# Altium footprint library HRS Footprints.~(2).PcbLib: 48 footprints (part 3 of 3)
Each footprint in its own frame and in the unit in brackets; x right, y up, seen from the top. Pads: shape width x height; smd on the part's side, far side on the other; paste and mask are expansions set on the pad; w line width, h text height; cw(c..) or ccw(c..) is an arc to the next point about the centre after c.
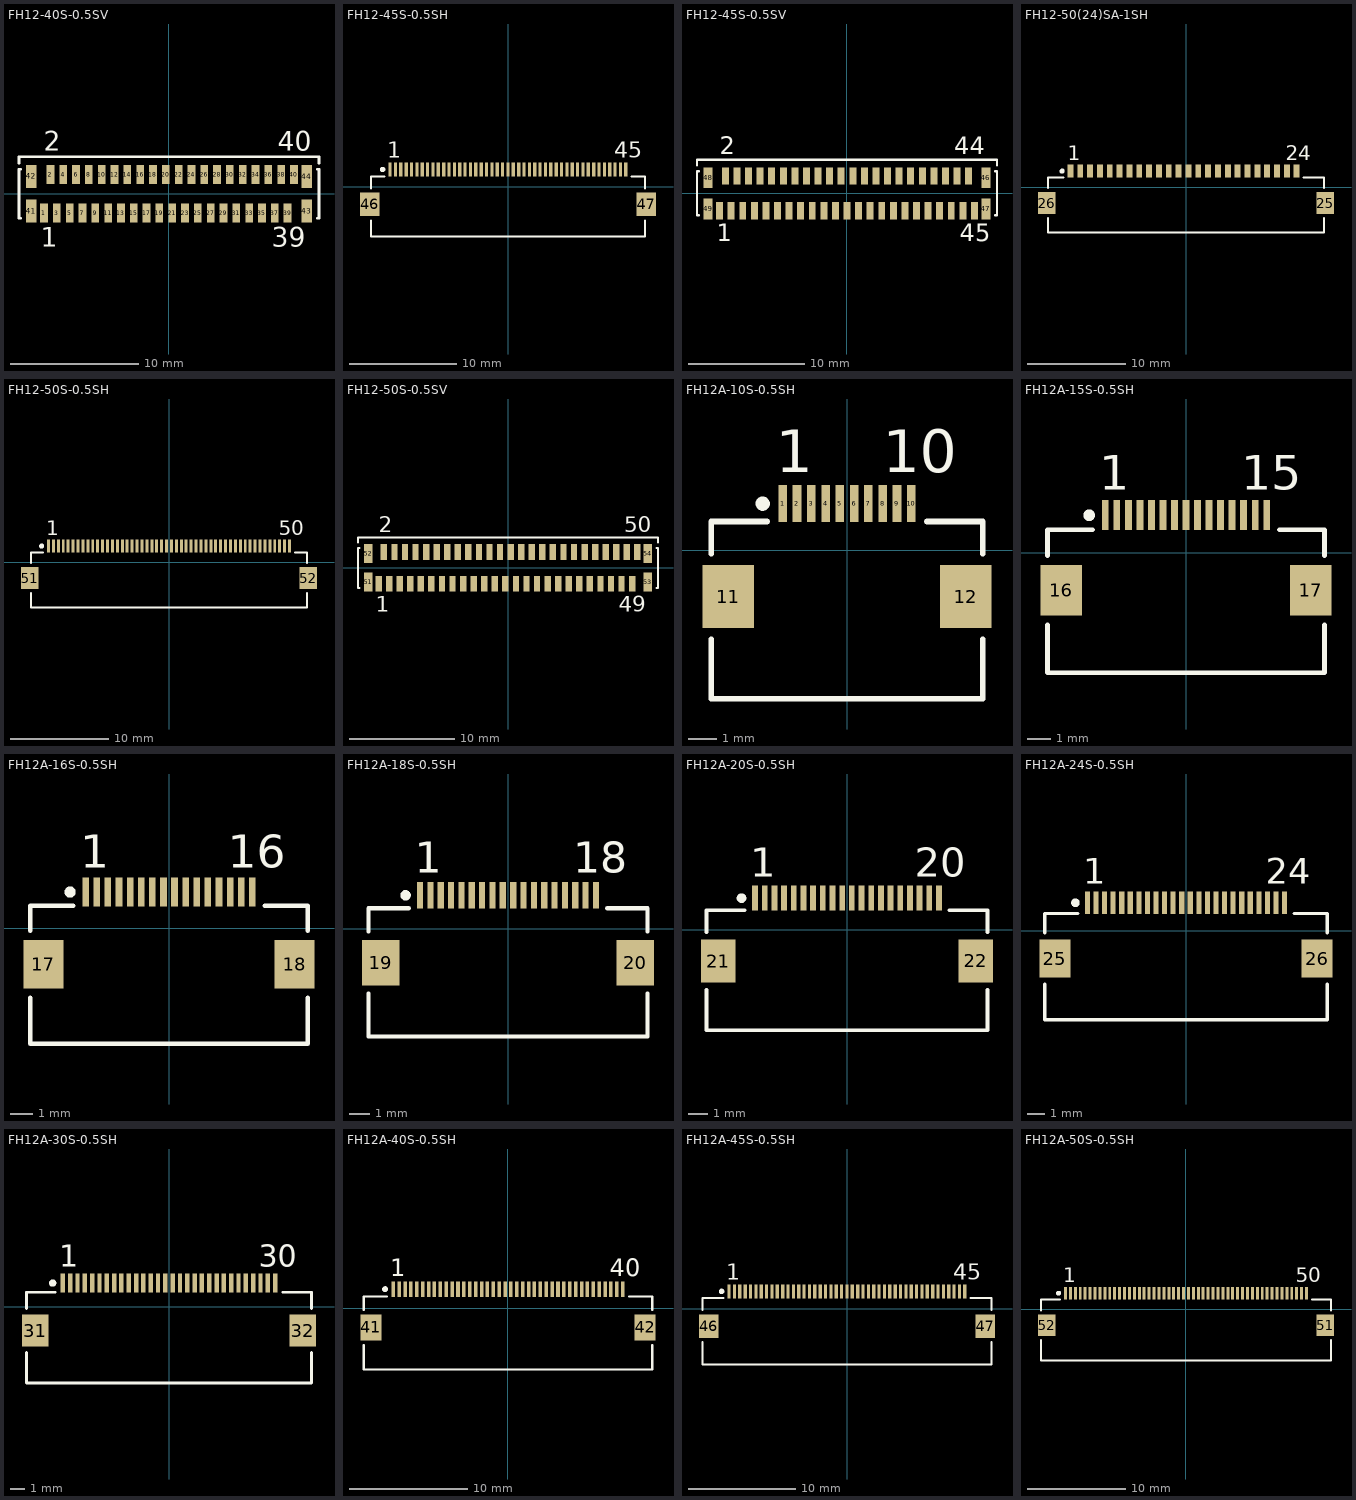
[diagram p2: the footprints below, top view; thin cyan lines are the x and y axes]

## FH12-40S-0.5SV [mm] "Connector; FH12 Series; 40 Position; 0.5mm Spaced Vertical Mounting"
height 4.85
pads (44):
  rect 0.6x1.5 smd: 1(-9.75,-1.5) 2(-9.25,1.5) 3(-8.75,-1.5) 4(-8.25,1.5) 5(-7.75,-1.5) 6(-7.25,1.5) 7(-6.75,-1.5) 8(-6.25,1.5) 9(-5.75,-1.5) 10(-5.25,1.5) 11(-4.75,-1.5) 12(-4.25,1.5) 13(-3.75,-1.5) 14(-3.25,1.5) 15(-2.75,-1.5) 16(-2.25,1.5) 17(-1.75,-1.5) 18(-1.25,1.5) 19(-0.75,-1.5) 20(-0.25,1.5) 21(0.25,-1.5) 22(0.75,1.5) 23(1.25,-1.5) 24(1.75,1.5) 25(2.25,-1.5) 26(2.75,1.5) 27(3.25,-1.5) 28(3.75,1.5) 29(4.25,-1.5) 30(4.75,1.5) 31(5.25,-1.5) 32(5.75,1.5) 33(6.25,-1.5) 34(6.75,1.5) 35(7.25,-1.5) 36(7.75,1.5) 37(8.25,-1.5) 38(8.75,1.5) 39(9.25,-1.5) 40(9.75,1.5)
  rect 0.8x1.8 smd: 41(-10.75,-1.35) 42(-10.75,1.35) 43(10.75,-1.35) 44(10.75,1.35)
Top Overlay:
  lines w0.2: -11.7,2.4 -11.7,2.9 11.7,2.9 11.7,2.4 ; -11.55,-1.9 -11.7,-1.9 -11.7,1.9 -11.55,1.9 ; 11.55,-1.9 11.7,-1.9 11.7,1.9 11.55,1.9
  text "39" at 8,-4.125 h1.5
  text "40" at 8.5,3.375 h1.5
  text "2" at -9.75,3.375 h1.5
  text "1" at -10,-4.125 h1.5

## FH12-45S-0.5SH [mm] "Connector; FH12 Series; 45 Position; 0.5mm Spaced Bottom Contact"
height 2
pads (47):
  rect 0.3x1.3 smd: 1(-11,1.625) 2(-10.5,1.625) 3(-10,1.625) 4(-9.5,1.625) 5(-9,1.625) 6(-8.5,1.625) 7(-8,1.625) 8(-7.5,1.625) 9(-7,1.625) 10(-6.5,1.625) 11(-6,1.625) 12(-5.5,1.625) 13(-5,1.625) 14(-4.5,1.625) 15(-4,1.625) 16(-3.5,1.625) 17(-3,1.625) 18(-2.5,1.625) 19(-2,1.625) 20(-1.5,1.625) 21(-1,1.625) 22(-0.5,1.625) 23(0,1.625) 24(0.5,1.625) 25(1,1.625) 26(1.5,1.625) 27(2,1.625) 28(2.5,1.625) 29(3,1.625) 30(3.5,1.625) 31(4,1.625) 32(4.5,1.625) 33(5,1.625) 34(5.5,1.625) 35(6,1.625) 36(6.5,1.625) 37(7,1.625) 38(7.5,1.625) 39(8,1.625) 40(8.5,1.625) 41(9,1.625) 42(9.5,1.625) 43(10,1.625) 44(10.5,1.625) 45(11,1.625)
  rect 1.8x2.2 smd: 46(-12.9,-1.625) 47(12.9,-1.625)
Top Overlay:
  circle w0.25: c-11.7,1.625 r0.125
  lines w0.2: -12.8,-3.125 -12.8,-4.625 12.8,-4.625 12.8,-3.125 ; -12.8,-0.125 -12.8,0.975 -11.55,0.975 ; 11.55,0.975 12.8,0.975 12.8,-0.125
  text "1" at -11.25,2.725 h1.5
  text "45" at 9.9,2.725 h1.5

## FH12-45S-0.5SV [mm] "Connector; FH12 Series; 45 Position; 0.5mm Spaced Vertical Mounting"
height 4.85
pads (49):
  rect 0.6x1.5 smd: 1(-11,-1.5) 2(-10.5,1.5) 3(-10,-1.5) 4(-9.5,1.5) 5(-9,-1.5) 6(-8.5,1.5) 7(-8,-1.5) 8(-7.5,1.5) 9(-7,-1.5) 10(-6.5,1.5) 11(-6,-1.5) 12(-5.5,1.5) 13(-5,-1.5) 14(-4.5,1.5) 15(-4,-1.5) 16(-3.5,1.5) 17(-3,-1.5) 18(-2.5,1.5) 19(-2,-1.5) 20(-1.5,1.5) 21(-1,-1.5) 22(-0.5,1.5) 23(0,-1.5) 24(0.5,1.5) 25(1,-1.5) 26(1.5,1.5) 27(2,-1.5) 28(2.5,1.5) 29(3,-1.5) 30(3.5,1.5) 31(4,-1.5) 32(4.5,1.5) 33(5,-1.5) 34(5.5,1.5) 35(6,-1.5) 36(6.5,1.5) 37(7,-1.5) 38(7.5,1.5) 39(8,-1.5) 40(8.5,1.5) 41(9,-1.5) 42(9.5,1.5) 43(10,-1.5) 44(10.5,1.5) 45(11,-1.5)
  rect 0.8x1.8 smd: 46(12,1.35) 47(12,-1.35) 48(-12,1.35) 49(-12,-1.35)
Top Overlay:
  lines w0.2: -12.95,2.4 -12.95,2.9 12.95,2.9 12.95,2.4 ; -12.8,-1.9 -12.95,-1.9 -12.95,1.9 -12.8,1.9 ; 12.8,-1.9 12.95,-1.9 12.95,1.9 12.8,1.9
  text "45" at 9.75,-4.125 h1.5
  text "44" at 9.25,3.375 h1.5
  text "1" at -11.25,-4.125 h1.5
  text "2" at -11,3.375 h1.5

## FH12-50(24)SA-1SH [mm] "Connector; FH12 Series; 24 Position; 1.0mm Spaced Bottom Eccentric Contact"
height 2
pads (26):
  rect 0.6x1.3 smd: 1(-11.75,1.625) 2(-10.75,1.625) 3(-9.75,1.625) 4(-8.75,1.625) 5(-7.75,1.625) 6(-6.75,1.625) 7(-5.75,1.625) 8(-4.75,1.625) 9(-3.75,1.625) 10(-2.75,1.625) 11(-1.75,1.625) 12(-0.75,1.625) 13(0.25,1.625) 14(1.25,1.625) 15(2.25,1.625) 16(3.25,1.625) 17(4.25,1.625) 18(5.25,1.625) 19(6.25,1.625) 20(7.25,1.625) 21(8.25,1.625) 22(9.25,1.625) 23(10.25,1.625) 24(11.25,1.625)
  rect 1.8x2.2 smd: 25(14.15,-1.625) 26(-14.15,-1.625)
Top Overlay:
  circle w0.25: c-12.6,1.625 r0.125
  lines w0.2: -14.05,-3.125 -14.05,-4.625 14.05,-4.625 14.05,-3.125 ; -14.05,-0.125 -14.05,0.975 -12.45,0.975 ; 11.95,0.975 14.05,0.975 14.05,-0.125
  text "24" at 10.15,2.725 h1.5
  text "1" at -12,2.725 h1.5

## FH12-50S-0.5SH [mm] "Connector; FH12 Series; 50 Position; 0.5mm Spaced Bottom Contact"
height 2
pads (52):
  rect 0.3x1.3 smd: 1(-12.25,1.625) 2(-11.75,1.625) 3(-11.25,1.625) 4(-10.75,1.625) 5(-10.25,1.625) 6(-9.75,1.625) 7(-9.25,1.625) 8(-8.75,1.625) 9(-8.25,1.625) 10(-7.75,1.625) 11(-7.25,1.625) 12(-6.75,1.625) 13(-6.25,1.625) 14(-5.75,1.625) 15(-5.25,1.625) 16(-4.75,1.625) 17(-4.25,1.625) 18(-3.75,1.625) 19(-3.25,1.625) 20(-2.75,1.625) 21(-2.25,1.625) 22(-1.75,1.625) 23(-1.25,1.625) 24(-0.75,1.625) 25(-0.25,1.625) 26(0.25,1.625) 27(0.75,1.625) 28(1.25,1.625) 29(1.75,1.625) 30(2.25,1.625) 31(2.75,1.625) 32(3.25,1.625) 33(3.75,1.625) 34(4.25,1.625) 35(4.75,1.625) 36(5.25,1.625) 37(5.75,1.625) 38(6.25,1.625) 39(6.75,1.625) 40(7.25,1.625) 41(7.75,1.625) 42(8.25,1.625) 43(8.75,1.625) 44(9.25,1.625) 45(9.75,1.625) 46(10.25,1.625) 47(10.75,1.625) 48(11.25,1.625) 49(11.75,1.625) 50(12.25,1.625)
  rect 1.8x2.2 smd: 51(-14.15,-1.625) 52(14.15,-1.625)
Top Overlay:
  circle w0.25: c-12.95,1.625 r0.125
  lines w0.2: -14.05,-3.125 -14.05,-4.625 14.05,-4.625 14.05,-3.125 ; -14.05,-0.125 -14.05,0.975 -12.8,0.975 ; 12.8,0.975 14.05,0.975 14.05,-0.125
  text "50" at 11.15,2.725 h1.5
  text "1" at -12.5,2.725 h1.5
3D body: height 2.04, standoff -0.06, extent -14.55,-4.699 14.55,1.701

## FH12-50S-0.5SV [mm] "Connector; FH12 Series; 50 Position; 0.5mm Spaced Vertical Mounting"
height 4.85
pads (54):
  rect 0.6x1.5 smd: 1(-12.25,-1.5) 2(-11.75,1.5) 3(-11.25,-1.5) 4(-10.75,1.5) 5(-10.25,-1.5) 6(-9.75,1.5) 7(-9.25,-1.5) 8(-8.75,1.5) 9(-8.25,-1.5) 10(-7.75,1.5) 11(-7.25,-1.5) 12(-6.75,1.5) 13(-6.25,-1.5) 14(-5.75,1.5) 15(-5.25,-1.5) 16(-4.75,1.5) 17(-4.25,-1.5) 18(-3.75,1.5) 19(-3.25,-1.5) 20(-2.75,1.5) 21(-2.25,-1.5) 22(-1.75,1.5) 23(-1.25,-1.5) 24(-0.75,1.5) 25(-0.25,-1.5) 26(0.25,1.5) 27(0.75,-1.5) 28(1.25,1.5) 29(1.75,-1.5) 30(2.25,1.5) 31(2.75,-1.5) 32(3.25,1.5) 33(3.75,-1.5) 34(4.25,1.5) 35(4.75,-1.5) 36(5.25,1.5) 37(5.75,-1.5) 38(6.25,1.5) 39(6.75,-1.5) 40(7.25,1.5) 41(7.75,-1.5) 42(8.25,1.5) 43(8.75,-1.5) 44(9.25,1.5) 45(9.75,-1.5) 46(10.25,1.5) 47(10.75,-1.5) 48(11.25,1.5) 49(11.75,-1.5) 50(12.25,1.5)
  rect 0.8x1.8 smd: 51(-13.25,-1.35) 52(-13.25,1.35) 53(13.25,-1.35) 54(13.25,1.35)
Top Overlay:
  lines w0.2: -14.2,2.4 -14.2,2.9 14.2,2.9 14.2,2.4 ; -14.05,-1.9 -14.2,-1.9 -14.2,1.9 -14.05,1.9 ; 14.05,-1.9 14.2,-1.9 14.2,1.9 14.05,1.9
  text "50" at 11,3.375 h1.5
  text "49" at 10.5,-4.125 h1.5
  text "2" at -12.25,3.375 h1.5
  text "1" at -12.5,-4.125 h1.5

## FH12A-10S-0.5SH [mm] "Connector; FH12 Series; 10 Position; 0.5mm Spaced Top Contact"
height 2
pads (12):
  rect 0.3x1.3 smd: 1(-2.25,1.625) 2(-1.75,1.625) 3(-1.25,1.625) 4(-0.75,1.625) 5(-0.25,1.625) 6(0.25,1.625) 7(0.75,1.625) 8(1.25,1.625) 9(1.75,1.625) 10(2.25,1.625)
  rect 1.8x2.2 smd: 11(-4.15,-1.625) 12(4.15,-1.625)
Top Overlay:
  circle w0.25: c-2.95,1.625 r0.125
  lines w0.2: -4.75,-3.125 -4.75,-5.2 4.75,-5.2 4.75,-3.125 ; -4.75,-0.125 -4.75,1 -2.8,1 ; 2.8,1 4.75,1 4.75,-0.125
  text "10" at 1.25,2.725 h1.5
  text "1" at -2.5,2.725 h1.5

## FH12A-15S-0.5SH [mm] "Connector; FH12 Series; 15 Position; 0.5mm Spaced Top Contact"
height 2
pads (17):
  rect 0.3x1.3 smd: 1(-3.5,1.625) 2(-3,1.625) 3(-2.5,1.625) 4(-2,1.625) 5(-1.5,1.625) 6(-1,1.625) 7(-0.5,1.625) 8(0,1.625) 9(0.5,1.625) 10(1,1.625) 11(1.5,1.625) 12(2,1.625) 13(2.5,1.625) 14(3,1.625) 15(3.5,1.625)
  rect 1.8x2.2 smd: 16(-5.4,-1.625) 17(5.4,-1.625)
Top Overlay:
  circle w0.25: c-4.2,1.625 r0.125
  lines w0.2: -6,-3.125 -6,-5.2 6,-5.2 6,-3.125 ; -6,-0.125 -6,1 -4.05,1 ; 4.05,1 6,1 6,-0.125
  text "1" at -3.75,2.725 h1.5
  text "15" at 2.4,2.725 h1.5

## FH12A-16S-0.5SH [mm] "Connector; FH12 Series; 16 Position; 0.5mm Spaced Top Contact"
height 2
pads (18):
  rect 0.3x1.3 smd: 1(-3.75,1.625) 2(-3.25,1.625) 3(-2.75,1.625) 4(-2.25,1.625) 5(-1.75,1.625) 6(-1.25,1.625) 7(-0.75,1.625) 8(-0.25,1.625) 9(0.25,1.625) 10(0.75,1.625) 11(1.25,1.625) 12(1.75,1.625) 13(2.25,1.625) 14(2.75,1.625) 15(3.25,1.625) 16(3.75,1.625)
  rect 1.8x2.2 smd: 17(-5.65,-1.625) 18(5.65,-1.625)
Top Overlay:
  circle w0.25: c-4.45,1.625 r0.125
  lines w0.2: -6.25,-3.125 -6.25,-5.2 6.25,-5.2 6.25,-3.125 ; -6.25,-0.125 -6.25,1 -4.3,1 ; 4.3,1 6.25,1 6.25,-0.125
  text "16" at 2.65,2.725 h1.5
  text "1" at -4,2.725 h1.5

## FH12A-18S-0.5SH [mm] "Connector; FH12 Series; 18 Position; 0.5mm Spaced Top Contact"
height 2
pads (20):
  rect 0.3x1.3 smd: 1(-4.25,1.625) 2(-3.75,1.625) 3(-3.25,1.625) 4(-2.75,1.625) 5(-2.25,1.625) 6(-1.75,1.625) 7(-1.25,1.625) 8(-0.75,1.625) 9(-0.25,1.625) 10(0.25,1.625) 11(0.75,1.625) 12(1.25,1.625) 13(1.75,1.625) 14(2.25,1.625) 15(2.75,1.625) 16(3.25,1.625) 17(3.75,1.625) 18(4.25,1.625)
  rect 1.8x2.2 smd: 19(-6.15,-1.625) 20(6.15,-1.625)
Top Overlay:
  circle w0.25: c-4.95,1.625 r0.125
  lines w0.2: -6.75,-3.125 -6.75,-5.2 6.75,-5.2 6.75,-3.125 ; -6.75,-0.125 -6.75,1 -4.8,1 ; 4.8,1 6.75,1 6.75,-0.125
  text "1" at -4.5,2.725 h1.5
  text "18" at 3.15,2.725 h1.5

## FH12A-20S-0.5SH [mm] "Connector; FH12 Series; 20 Position; 0.5mm Spaced Top Contact"
height 2
pads (22):
  rect 0.3x1.3 smd: 1(-4.75,1.625) 2(-4.25,1.625) 3(-3.75,1.625) 4(-3.25,1.625) 5(-2.75,1.625) 6(-2.25,1.625) 7(-1.75,1.625) 8(-1.25,1.625) 9(-0.75,1.625) 10(-0.25,1.625) 11(0.25,1.625) 12(0.75,1.625) 13(1.25,1.625) 14(1.75,1.625) 15(2.25,1.625) 16(2.75,1.625) 17(3.25,1.625) 18(3.75,1.625) 19(4.25,1.625) 20(4.75,1.625)
  rect 1.8x2.2 smd: 21(-6.65,-1.625) 22(6.65,-1.623)
Top Overlay:
  circle w0.25: c-5.45,1.625 r0.125
  lines w0.2: -7.25,-3.123 -7.25,-5.198 7.25,-5.198 7.25,-3.123 ; -7.25,-0.123 -7.25,1.002 -5.3,1.002 ; 5.3,1.002 7.25,1.002 7.25,-0.123
  text "20" at 3.5,2.725 h1.5
  text "1" at -5,2.725 h1.5

## FH12A-24S-0.5SH [mm] "Connector; FH12 Series; 24 Position; 0.5mm Spaced Top Contact"
height 2
pads (26):
  rect 0.3x1.3 smd: 1(-5.75,1.625) 2(-5.25,1.625) 3(-4.75,1.625) 4(-4.25,1.625) 5(-3.75,1.625) 6(-3.25,1.625) 7(-2.75,1.625) 8(-2.25,1.625) 9(-1.75,1.625) 10(-1.25,1.625) 11(-0.75,1.625) 12(-0.25,1.625) 13(0.25,1.625) 14(0.75,1.625) 15(1.25,1.625) 16(1.75,1.625) 17(2.25,1.625) 18(2.75,1.625) 19(3.25,1.625) 20(3.75,1.625) 21(4.25,1.625) 22(4.75,1.625) 23(5.25,1.625) 24(5.75,1.625)
  rect 1.8x2.2 smd: 25(-7.65,-1.625) 26(7.65,-1.625)
Top Overlay:
  circle w0.25: c-6.45,1.625 r0.125
  lines w0.2: -8.25,-3.125 -8.25,-5.2 8.25,-5.2 8.25,-3.125 ; -8.25,-0.125 -8.25,1 -6.3,1 ; 6.3,1 8.25,1 8.25,-0.125
  text "24" at 4.65,2.725 h1.5
  text "1" at -6,2.725 h1.5

## FH12A-30S-0.5SH [mm] "Connector; FH12 Series; 30 Position; 0.5mm Spaced Top Contact"
height 2
pads (32):
  rect 0.3x1.3 smd: 1(-7.25,1.625) 2(-6.75,1.625) 3(-6.25,1.625) 4(-5.75,1.625) 5(-5.25,1.625) 6(-4.75,1.625) 7(-4.25,1.625) 8(-3.75,1.625) 9(-3.25,1.625) 10(-2.75,1.625) 11(-2.25,1.625) 12(-1.75,1.625) 13(-1.25,1.625) 14(-0.75,1.625) 15(-0.25,1.625) 16(0.25,1.625) 17(0.75,1.625) 18(1.25,1.625) 19(1.75,1.625) 20(2.25,1.625) 21(2.75,1.625) 22(3.25,1.625) 23(3.75,1.625) 24(4.25,1.625) 25(4.75,1.625) 26(5.25,1.625) 27(5.75,1.625) 28(6.25,1.625) 29(6.75,1.625) 30(7.25,1.625)
  rect 1.8x2.2 smd: 31(-9.15,-1.625) 32(9.15,-1.625)
Top Overlay:
  circle w0.25: c-7.95,1.625 r0.125
  lines w0.2: -9.75,-3.125 -9.75,-5.2 9.75,-5.2 9.75,-3.125 ; -9.75,-0.125 -9.75,1 -7.8,1 ; 7.8,1 9.75,1 9.75,-0.125
  text "1" at -7.5,2.725 h1.5
  text "30" at 6.15,2.725 h1.5

## FH12A-40S-0.5SH [mm] "Connector; FH12 Series; 40 Position; 0.5mm Spaced Top Contact"
height 2
pads (42):
  rect 0.3x1.3 smd: 1(-9.75,1.625) 2(-9.25,1.625) 3(-8.75,1.625) 4(-8.25,1.625) 5(-7.75,1.625) 6(-7.25,1.625) 7(-6.75,1.625) 8(-6.25,1.625) 9(-5.75,1.625) 10(-5.25,1.625) 11(-4.75,1.625) 12(-4.25,1.625) 13(-3.75,1.625) 14(-3.25,1.625) 15(-2.75,1.625) 16(-2.25,1.625) 17(-1.75,1.625) 18(-1.25,1.625) 19(-0.75,1.625) 20(-0.25,1.625) 21(0.25,1.625) 22(0.75,1.625) 23(1.25,1.625) 24(1.75,1.625) 25(2.25,1.625) 26(2.75,1.625) 27(3.25,1.625) 28(3.75,1.625) 29(4.25,1.625) 30(4.75,1.625) 31(5.25,1.625) 32(5.75,1.625) 33(6.25,1.625) 34(6.75,1.625) 35(7.25,1.625) 36(7.75,1.625) 37(8.25,1.625) 38(8.75,1.625) 39(9.25,1.625) 40(9.75,1.625)
  rect 1.8x2.2 smd: 41(-11.65,-1.625) 42(11.65,-1.625)
Top Overlay:
  circle w0.25: c-10.45,1.625 r0.125
  lines w0.2: -12.25,-3.125 -12.25,-5.2 12.25,-5.2 12.25,-3.125 ; -12.25,-0.125 -12.25,1 -10.3,1 ; 10.3,1 12.25,1 12.25,-0.125
  text "40" at 8.65,2.725 h1.5
  text "1" at -10,2.725 h1.5

## FH12A-45S-0.5SH [mm] "Connector; FH12 Series; 45 Position; 0.5mm Spaced Top Contact"
height 2
pads (47):
  rect 0.3x1.3 smd: 1(-11,1.625) 2(-10.5,1.625) 3(-10,1.625) 4(-9.5,1.625) 5(-9,1.625) 6(-8.5,1.625) 7(-8,1.625) 8(-7.5,1.625) 9(-7,1.625) 10(-6.5,1.625) 11(-6,1.625) 12(-5.5,1.625) 13(-5,1.625) 14(-4.5,1.625) 15(-4,1.625) 16(-3.5,1.625) 17(-3,1.625) 18(-2.5,1.625) 19(-2,1.625) 20(-1.5,1.625) 21(-1,1.625) 22(-0.5,1.625) 23(0,1.625) 24(0.5,1.625) 25(1,1.625) 26(1.5,1.625) 27(2,1.625) 28(2.5,1.625) 29(3,1.625) 30(3.5,1.625) 31(4,1.625) 32(4.5,1.625) 33(5,1.625) 34(5.5,1.625) 35(6,1.625) 36(6.5,1.625) 37(7,1.625) 38(7.5,1.625) 39(8,1.625) 40(8.5,1.625) 41(9,1.625) 42(9.5,1.625) 43(10,1.625) 44(10.5,1.625) 45(11,1.625)
  rect 1.8x2.2 smd: 46(-12.9,-1.625) 47(12.9,-1.625)
Top Overlay:
  circle w0.25: c-11.7,1.625 r0.125
  lines w0.2: -13.5,-3.125 -13.5,-5.2 13.5,-5.2 13.5,-3.125 ; -13.5,-0.125 -13.5,1 -11.55,1 ; 11.55,1 13.5,1 13.5,-0.125
  text "45" at 9.9,2.725 h1.5
  text "1" at -11.25,2.725 h1.5

## FH12A-50S-0.5SH [mm] "Connector; FH12 Series; 50 Position; 0.5mm Spaced Top Contact"
height 2
pads (52):
  rect 0.3x1.3 smd: 1(-12.25,1.625) 2(-11.75,1.625) 3(-11.25,1.625) 4(-10.75,1.625) 5(-10.25,1.625) 6(-9.75,1.625) 7(-9.25,1.625) 8(-8.75,1.625) 9(-8.25,1.625) 10(-7.75,1.625) 11(-7.25,1.625) 12(-6.75,1.625) 13(-6.25,1.625) 14(-5.75,1.625) 15(-5.25,1.625) 16(-4.75,1.625) 17(-4.25,1.625) 18(-3.75,1.625) 19(-3.25,1.625) 20(-2.75,1.625) 21(-2.25,1.625) 22(-1.75,1.625) 23(-1.25,1.625) 24(-0.75,1.625) 25(-0.25,1.625) 26(0.25,1.625) 27(0.75,1.625) 28(1.25,1.625) 29(1.75,1.625) 30(2.25,1.625) 31(2.75,1.625) 32(3.25,1.625) 33(3.75,1.625) 34(4.25,1.625) 35(4.75,1.625) 36(5.25,1.625) 37(5.75,1.625) 38(6.25,1.625) 39(6.75,1.625) 40(7.25,1.625) 41(7.75,1.625) 42(8.25,1.625) 43(8.75,1.625) 44(9.25,1.625) 45(9.75,1.625) 46(10.25,1.625) 47(10.75,1.625) 48(11.25,1.625) 49(11.75,1.625) 50(12.25,1.625)
  rect 1.8x2.2 smd: 51(14.15,-1.625) 52(-14.15,-1.625)
Top Overlay:
  circle w0.25: c-12.95,1.625 r0.125
  lines w0.2: -14.75,-3.125 -14.75,-5.2 14.75,-5.2 14.75,-3.125 ; -14.75,-0.125 -14.75,1 -12.8,1 ; 12.8,1 14.75,1 14.75,-0.125
  text "1" at -12.5,2.725 h1.5
  text "50" at 11.15,2.725 h1.5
